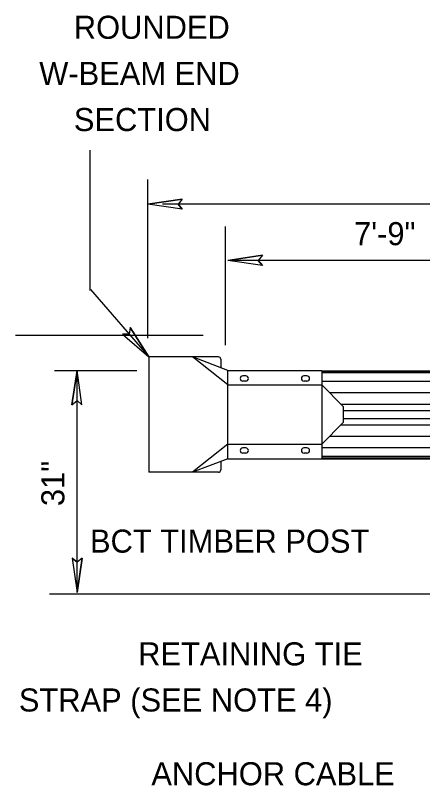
# Model space of a CAD drawing. Extents: x 12.2 to 54.5, y -7.8 to 16.1.
# Drawn here: x 12.308 to 13.367, y 14.138 to 16.141 of the extents above; entities that cross this region are included whole.
import ezdxf

# ---------------------------------------------------------------- set-up
doc = ezdxf.new("R2010")
doc.units = 0
for name, color, linetype in [('BORD-LINE', 7, 'Continuous'), ('DETL-DIMS', 7, 'Continuous'), ('DETL-NOTE', 7, 'Continuous')]:
    doc.layers.add(name, color=color, linetype=linetype)

msp = doc.modelspace()

# ---------------------------------------------------------------- linework, layer by layer
at = {"layer": 'BORD-LINE'}
for p, q in [((12.7962, 15.3088), (12.3076, 15.3088)), ((12.8356, 15.2533), (12.6544, 15.2533)), ((12.6544, 15.2533), (12.6544, 14.9533)), ((12.8606, 15.2181), (12.7686, 15.2533)), ((12.8606, 15.1806), (12.7686, 15.2533)), ((12.8419, 15.247), (12.8419, 15.2253)), ((12.8606, 15.2157), (12.8606, 15.2181)), ((12.8606, 15.2181), (13.1044, 15.2181)), ((12.8606, 15.1806), (12.8606, 15.2181)), ((12.8606, 15.2124), (12.8606, 15.2157)), ((12.8606, 15.2114), (12.8606, 15.2124)), ((12.8606, 15.1888), (12.8606, 15.2114)), ((13.1044, 15.2181), (13.1044, 15.1806)), ((13.645, 15.2157), (13.1044, 15.2157)), ((13.645, 15.2124), (13.1044, 15.2124)), ((13.645, 15.2114), (13.1044, 15.2114)), ((12.8606, 15.1599), (12.8606, 15.1888)), ((12.9067, 15.2038), (12.8989, 15.2038)), ((12.9067, 15.1902), (12.899, 15.1902)), ((13.0661, 15.2038), (13.0583, 15.2038)), ((13.066, 15.1902), (13.0583, 15.1902)), ((13.645, 15.1888), (13.1044, 15.1888)), ((12.8606, 15.1806), (13.1044, 15.1806)), ((13.1044, 15.1806), (13.1606, 15.1244)), ((13.1044, 15.1806), (13.1044, 15.0259)), ((12.8606, 15.1297), (12.8606, 15.1599)), ((13.645, 15.1599), (13.1251, 15.1599)), ((12.8606, 15.1131), (12.8606, 15.1297)), ((13.645, 15.1297), (13.1553, 15.1297)), ((13.1606, 15.1244), (13.1606, 15.0822)), ((12.8606, 15.0925), (12.8606, 15.1131)), ((13.645, 15.1131), (13.1606, 15.1131)), ((12.8606, 15.076), (12.8606, 15.0925)), ((13.645, 15.0925), (13.1606, 15.0925)), ((12.8606, 15.0457), (12.8606, 15.076)), ((13.1044, 15.0259), (13.1606, 15.0822)), ((13.645, 15.076), (13.1544, 15.076)), ((12.8606, 15.0169), (12.8606, 15.0457)), ((13.645, 15.0457), (13.1242, 15.0457)), ((12.8606, 15.0259), (12.7686, 14.9533)), ((12.8606, 15.0259), (13.1044, 15.0259)), ((12.8606, 14.9884), (12.8606, 15.0259)), ((13.1044, 15.0259), (13.1044, 14.9884)), ((12.8606, 14.9942), (12.8606, 15.0169)), ((12.9067, 15.0163), (12.8989, 15.0163)), ((13.0661, 15.0163), (13.0583, 15.0163)), ((13.645, 15.0169), (13.1044, 15.0169)), ((12.8606, 14.9884), (12.7686, 14.9533)), ((12.8606, 14.9933), (12.8606, 14.9942)), ((12.8606, 14.99), (12.8606, 14.9933)), ((12.8606, 14.9875), (12.8606, 14.99)), ((12.8606, 14.9884), (13.1044, 14.9884)), ((12.873, 14.9884), (12.873, 14.9884)), ((12.9067, 15.0027), (12.899, 15.0027)), ((13.066, 15.0027), (13.0583, 15.0027)), ((13.645, 14.9942), (13.1044, 14.9942)), ((13.645, 14.99), (13.1044, 14.99)), ((13.645, 14.9875), (13.1044, 14.9875)), ((12.8419, 14.9813), (12.8419, 14.9595)), ((12.8356, 14.9533), (12.6544, 14.9533)), ((12.3965, 14.6369), (18.9405, 14.6369))]:
    msp.add_line(p, q, dxfattribs=at)
for centre, radius, start, end in [((12.8356, 15.247), 0.00625, 0, 90), ((12.899, 15.197), 0.0068, 90.1896, 270.0253), ((12.9067, 15.197), 0.0068, 269.9747, 89.8104), ((13.0583, 15.197), 0.0068, 90.1896, 270.0253), ((13.066, 15.197), 0.0068, 269.9747, 89.8104), ((12.899, 15.0095), 0.0068, 90.1896, 270.0253), ((12.9067, 15.0095), 0.0068, 269.9747, 89.8104), ((13.0583, 15.0095), 0.0068, 90.1896, 270.0253), ((13.066, 15.0095), 0.0068, 269.9747, 89.8104), ((12.8356, 14.9595), 0.00625, 270, 0)]:
    msp.add_arc(centre, radius, start, end, dxfattribs=at)
at = {"layer": 'DETL-DIMS'}
for p, q in [((12.5017, 15.426), (12.5017, 15.7908)), ((12.6522, 15.3015), (12.6522, 15.7149)), ((12.7418, 15.6633), (12.6522, 15.6501)), ((12.7418, 15.6372), (12.6522, 15.6501)), ((15.8032, 15.6501), (12.6898, 15.6501)), ((12.7418, 15.6633), (12.7307, 15.6501)), ((12.7418, 15.6372), (12.7307, 15.6501)), ((12.8535, 15.5919), (12.8535, 15.2836)), ((12.9502, 15.5174), (12.8606, 15.5042)), ((12.9502, 15.5174), (12.9391, 15.5042)), ((14.6003, 15.5042), (12.8606, 15.5042)), ((12.9502, 15.4913), (12.8606, 15.5042)), ((12.9502, 15.4913), (12.9391, 15.5042)), ((12.5033, 15.4285), (12.6544, 15.2533)), ((12.6059, 15.3298), (12.6031, 15.3127)), ((12.6059, 15.3298), (12.6544, 15.2533)), ((12.5861, 15.3127), (12.6544, 15.2533)), ((12.5861, 15.3127), (12.6031, 15.3127)), ((12.409, 15.2181), (12.6237, 15.2181)), ((12.4547, 15.1285), (12.4679, 15.2181)), ((12.4679, 14.6404), (12.4679, 15.2181)), ((12.4808, 15.1285), (12.4679, 15.2181)), ((12.4547, 15.1285), (12.4679, 15.1396)), ((12.4808, 15.1285), (12.4679, 15.1396)), ((12.455, 14.73), (12.4679, 14.6404)), ((12.455, 14.73), (12.4679, 14.7189)), ((12.4811, 14.73), (12.4679, 14.6404)), ((12.4811, 14.73), (12.4679, 14.7189))]:
    msp.add_line(p, q, dxfattribs=at)
for points in [[(12.7418, 15.6372), (12.6522, 15.6501), (12.7418, 15.6633), (12.7307, 15.6501)], [(12.9502, 15.4913), (12.8606, 15.5042), (12.9502, 15.5174), (12.9391, 15.5042)], [(12.5861, 15.3127), (12.6544, 15.2533), (12.6059, 15.3298), (12.6031, 15.3127)], [(12.4808, 15.1285), (12.4679, 15.2181), (12.4547, 15.1285), (12.4679, 15.1396)], [(12.455, 14.73), (12.4679, 14.6404), (12.4811, 14.73), (12.4679, 14.7189)]]:
    msp.add_lwpolyline(points, close=True, dxfattribs=at)

# ---------------------------------------------------------------- texts
at = {"layer": 'DETL-NOTE'}
for s, p in [('ROUNDED', (12.4596, 16.0805)), ('W-BEAM END', (12.3696, 15.9605)), ('SECTION', (12.4597, 15.8405)), ('7\'-9"', (13.1885, 15.5437)), ('BCT TIMBER POST', (12.5016, 14.744)), ('RETAINING TIE', (12.627, 14.4508)), ('STRAP (SEE NOTE 4)', (12.3166, 14.3308)), ('ANCHOR CABLE', (12.6613, 14.139))]:
    msp.add_text(s, height=0.06, dxfattribs=at).set_placement(p)
msp.add_text('31"', height=0.06, rotation=90, dxfattribs=at).set_placement((12.435, 14.8651))

doc.saveas('drawing.dxf')
